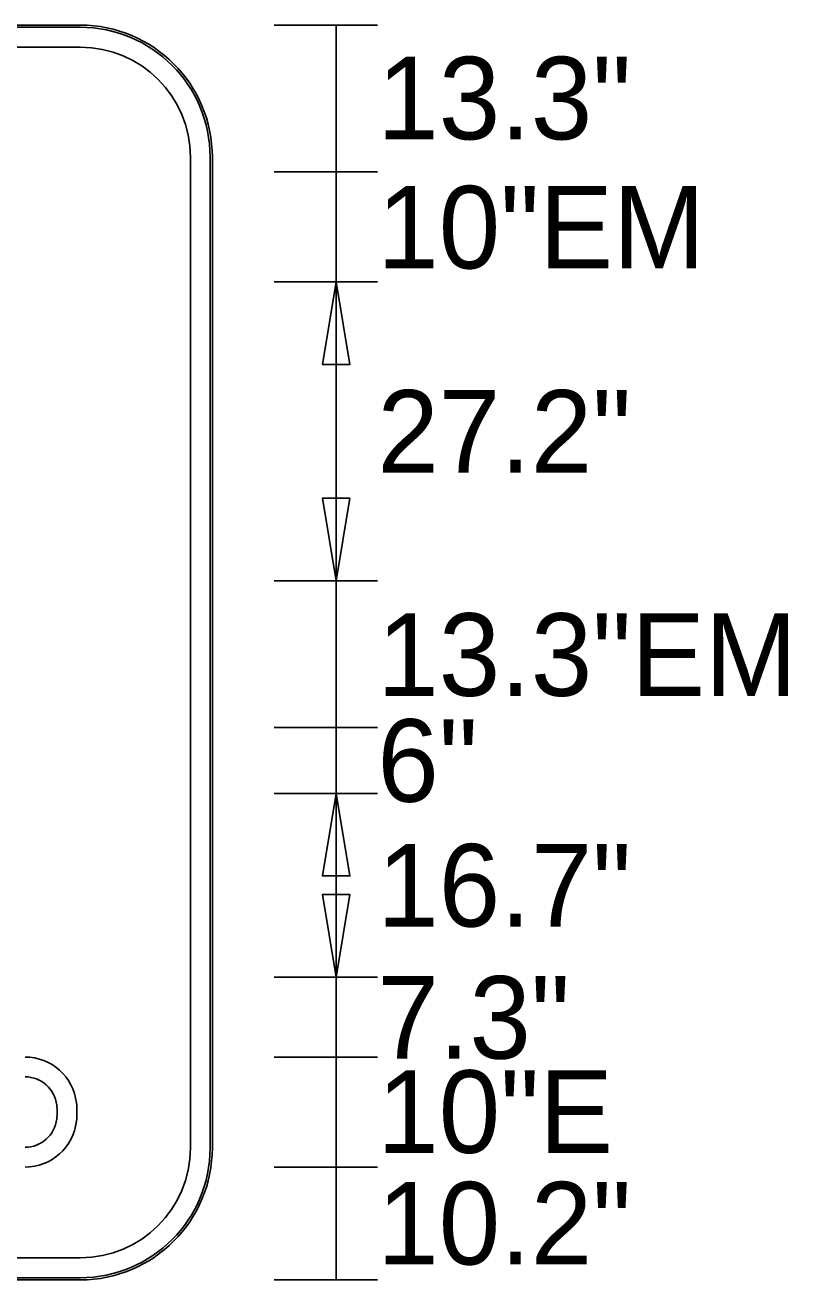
# Model space of a CAD drawing. Extents: x 1806251 to 1809821, y 414895 to 422886.
# Drawn here: x 1809678.146 to 1809678.839, y 414941.811 to 414942.951 of the extents above; entities that cross this region are included whole.
import ezdxf

# ---------------------------------------------------------------- set-up
doc = ezdxf.new("R2010")
doc.units = 0
for name, color, linetype in [('GSBWFILL', 7, 'Continuous'), ('GSCOLORFILL', 7, 'Continuous'), ('GSDIMS', 7, 'Continuous'), ('GSOUTLINE', 7, 'Continuous')]:
    doc.layers.add(name, color=color, linetype=linetype)

msp = doc.modelspace()

# ---------------------------------------------------------------- linework, layer by layer
at = {"layer": 'GSBWFILL'}
for p, q in [((1809678.196, 414942.951), (1809676.995, 414942.951)), ((1809676.995, 414942.931), (1809678.196, 414942.931)), ((1809678.296, 414942.831), (1809678.296, 414941.931)), ((1809678.316, 414941.931), (1809678.316, 414942.831)), ((1809678.196, 414941.831), (1809676.9952, 414941.831)), ((1809676.9952, 414941.811), (1809678.196, 414941.811))]:
    msp.add_line(p, q, dxfattribs=at)
for centre, radius, start, end in [((1809678.196, 414942.831), 0.12, 0, 90), ((1809678.196, 414942.831), 0.1, 0, 90), ((1809678.196, 414941.931), 0.12, 270, 0), ((1809678.196, 414941.931), 0.1, 270, 0)]:
    msp.add_arc(centre, radius, start, end, dxfattribs=at)
for centre, major_axis, start_param, end_param in [((1809678.1458, 414941.9665), (0, 0.047), 4.82584, 6.283185), ((1809678.1458, 414941.9665), (0, 0.029), 4.82584, 6.283185), ((1809678.1195, 414941.9635), (0, 0.0555), 4.598938, 4.82584), ((1809678.1195, 414941.9635), (0, 0.0735), 4.598938, 4.82584), ((1809678.1458, 414941.9605), (0, 0.029), 3.141593, 4.598938), ((1809678.1458, 414941.9605), (0, 0.047), 3.141593, 4.598938)]:
    msp.add_ellipse(centre, major_axis=major_axis, ratio=0.999994, start_param=start_param, end_param=end_param, dxfattribs=at)
at = {"layer": 'GSCOLORFILL'}
for p, q in [((1809678.196, 414942.951), (1809676.995, 414942.951)), ((1809678.196, 414942.951), (1809676.995, 414942.951)), ((1809678.196, 414942.951), (1809676.995, 414942.951)), ((1809676.995, 414942.949), (1809678.196, 414942.949)), ((1809676.995, 414942.931), (1809678.196, 414942.931)), ((1809678.296, 414942.831), (1809678.296, 414941.931)), ((1809678.314, 414942.831), (1809678.314, 414941.931)), ((1809678.316, 414941.931), (1809678.316, 414942.831)), ((1809678.316, 414941.931), (1809678.316, 414942.831)), ((1809678.316, 414941.931), (1809678.316, 414942.831)), ((1809678.196, 414941.831), (1809676.9952, 414941.831)), ((1809678.196, 414941.813), (1809676.995, 414941.813)), ((1809676.995, 414941.811), (1809678.196, 414941.811)), ((1809676.995, 414941.811), (1809678.196, 414941.811)), ((1809676.9952, 414941.811), (1809678.196, 414941.811))]:
    msp.add_line(p, q, dxfattribs=at)
for centre, radius, start, end in [((1809678.196, 414942.831), 0.12, 0, 90), ((1809678.196, 414942.831), 0.12, 0, 90), ((1809678.196, 414942.831), 0.12, 0, 90), ((1809678.196, 414942.831), 0.118, 0, 90), ((1809678.196, 414942.831), 0.1, 0, 90), ((1809678.196, 414941.931), 0.12, 270, 0), ((1809678.196, 414941.931), 0.12, 270, 0), ((1809678.196, 414941.931), 0.1, 270, 0), ((1809678.196, 414941.931), 0.12, 270, 0), ((1809678.196, 414941.931), 0.118, 270, 0)]:
    msp.add_arc(centre, radius, start, end, dxfattribs=at)
for centre, major_axis, start_param, end_param in [((1809678.1458, 414941.9665), (0, 0.047), 4.82584, 6.283185), ((1809678.1458, 414941.9665), (0, 0.029), 4.82584, 6.283185), ((1809678.1195, 414941.9635), (0, 0.0555), 4.598938, 4.82584), ((1809678.1195, 414941.9635), (0, 0.0735), 4.598938, 4.82584), ((1809678.1458, 414941.9605), (0, 0.029), 3.141593, 4.598938), ((1809678.1458, 414941.9605), (0, 0.047), 3.141593, 4.598938)]:
    msp.add_ellipse(centre, major_axis=major_axis, ratio=0.999994, start_param=start_param, end_param=end_param, dxfattribs=at)
at = {"layer": 'GSDIMS'}
for p, q in [((1809678.3723, 414942.951), (1809678.466, 414942.951)), ((1809678.4285, 414942.8177), (1809678.4285, 414942.951)), ((1809678.3723, 414942.8177), (1809678.466, 414942.8177)), ((1809678.3723, 414942.8177), (1809678.466, 414942.8177)), ((1809678.4285, 414942.8177), (1809678.4285, 414942.7177)), ((1809678.3723, 414942.7177), (1809678.466, 414942.7177)), ((1809678.3723, 414942.7177), (1809678.466, 414942.7177)), ((1809678.4285, 414942.4462), (1809678.4285, 414942.7177)), ((1809678.3723, 414942.4462), (1809678.466, 414942.4462)), ((1809678.3723, 414942.4462), (1809678.466, 414942.4462)), ((1809678.4285, 414942.4462), (1809678.4285, 414942.3129)), ((1809678.3723, 414942.3129), (1809678.466, 414942.3129)), ((1809678.3723, 414942.3129), (1809678.466, 414942.3129)), ((1809678.4285, 414942.253), (1809678.4285, 414942.3129)), ((1809678.3723, 414942.253), (1809678.466, 414942.253)), ((1809678.3723, 414942.253), (1809678.466, 414942.253)), ((1809678.4285, 414942.253), (1809678.4285, 414942.086)), ((1809678.3723, 414942.086), (1809678.466, 414942.086)), ((1809678.3723, 414942.086), (1809678.466, 414942.086)), ((1809678.4285, 414942.0135), (1809678.4285, 414942.086)), ((1809678.3723, 414942.0135), (1809678.466, 414942.0135)), ((1809678.3723, 414942.0135), (1809678.466, 414942.0135)), ((1809678.4285, 414942.0135), (1809678.4285, 414941.9135)), ((1809678.3723, 414941.9135), (1809678.466, 414941.9135)), ((1809678.3723, 414941.9135), (1809678.466, 414941.9135)), ((1809678.4285, 414941.811), (1809678.4285, 414941.9135)), ((1809678.3723, 414941.811), (1809678.466, 414941.811))]:
    msp.add_line(p, q, dxfattribs=at)
for points in [[(1809678.4285, 414942.7177), (1809678.416, 414942.6427), (1809678.441, 414942.6427)], [(1809678.4285, 414942.4462), (1809678.416, 414942.5212), (1809678.441, 414942.5212)], [(1809678.4285, 414942.253), (1809678.416, 414942.178), (1809678.441, 414942.178)], [(1809678.4285, 414942.086), (1809678.416, 414942.161), (1809678.441, 414942.161)]]:
    msp.add_lwpolyline(points, close=True, dxfattribs=at)
at = {"layer": 'GSOUTLINE'}
for p, q in [((1809678.196, 414942.951), (1809676.995, 414942.951)), ((1809678.196, 414942.931), (1809676.995, 414942.931)), ((1809678.296, 414941.931), (1809678.296, 414942.831)), ((1809678.316, 414941.931), (1809678.316, 414942.831)), ((1809676.995, 414941.831), (1809678.196, 414941.831)), ((1809676.995, 414941.811), (1809678.196, 414941.811))]:
    msp.add_line(p, q, dxfattribs=at)
for centre, radius, start, end in [((1809678.196, 414942.831), 0.12, 0, 90), ((1809678.196, 414942.831), 0.1, 0, 90), ((1809678.196, 414941.931), 0.12, 270, 0), ((1809678.196, 414941.931), 0.1, 270, 0)]:
    msp.add_arc(centre, radius, start, end, dxfattribs=at)
for centre, major_axis, start_param, end_param in [((1809678.1458, 414941.9665), (0, 0.047), 4.82584, 6.283185), ((1809678.1458, 414941.9665), (0, 0.029), 4.82584, 6.283185), ((1809678.1195, 414941.9635), (0, 0.0555), 4.598938, 4.82584), ((1809678.1195, 414941.9635), (0, 0.0735), 4.598938, 4.82584), ((1809678.1458, 414941.9605), (0, 0.029), 3.141593, 4.598938), ((1809678.1458, 414941.9605), (0, 0.047), 3.141593, 4.598938)]:
    msp.add_ellipse(centre, major_axis=major_axis, ratio=0.999994, start_param=start_param, end_param=end_param, dxfattribs=at)

# ---------------------------------------------------------------- texts
at = {"layer": 'GSDIMS'}
for s, p in [('13.3"', (1809678.466, 414942.8472)), ('10"EM', (1809678.466, 414942.7299)), ('27.2"', (1809678.466, 414942.5444)), ('13.3"EM', (1809678.466, 414942.3416)), ('6"', (1809678.466, 414942.2454)), ('16.7"', (1809678.466, 414942.132)), ('7.3"', (1809678.466, 414942.012)), ('10"E', (1809678.466, 414941.9264)), ('10.2"', (1809678.466, 414941.825))]:
    msp.add_text(s, height=0.075, dxfattribs=at).set_placement(p)

doc.saveas('drawing.dxf')
